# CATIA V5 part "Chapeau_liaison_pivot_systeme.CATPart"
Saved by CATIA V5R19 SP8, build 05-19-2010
Part number: Chapeau_liaison_pivot_systeme
Bounding box of the stored display mesh (mm): x -30 to 30, y -30 to 30, z 1240 to 1260
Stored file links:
  G:\EU_thinkMotion\CFAO_2010\MMS_groupe2\MMS_groupe2\OK\nrosalie\nrosalie_cfao_support_d_arme_legere_final\Chapeau_liaison_pivot_systeme.CATPart
  G:\EU_thinkMotion\CFAO_2010\MMS_groupe2\MMS_groupe2\OK\nrosalie\nrosalie_cfao_support_d_arme_legere_final\nrosalie_Support_d_arme_legere.CATProduct
  G:\EU_thinkMotion\CFAO_2010\MMS_groupe2\MMS_groupe2\OK\nrosalie\nrosalie_cfao_support_d_arme_legere_final\Squelette_Colone.CATPart
  G:\EU_thinkMotion\CFAO_2010\MMS_groupe2\MMS_groupe2\OK\nrosalie\nrosalie_cfao_support_d_arme_legere_final\Axe_liaison_pivot.CATPart
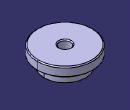
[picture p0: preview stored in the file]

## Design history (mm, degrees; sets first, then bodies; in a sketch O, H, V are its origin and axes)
Set1
  Sketch1 on Plane1, origin (0, 0, 1250), H (1, 0, 0), V (0, 1, 0)
    circle A1 centre (0, 0) radius 30
    reference projected point E1 (0, 0) from Point1
    radius A1 = 30
    concentricity: A1 E1
Set2
  Plane1 "Plan_limite_superieur_colonne": linked copy from another document
  Point1 "Centre_plan_limite_superieur_colonne": linked copy from another document
  DatumCurve1: linked copy from another document
Body1 (main body)
  Pad1: profile Sketch1, direction (0, 0, 1), length 10
  Sketch2 on end face of Pad1, origin (0, 0, 1260), H (1, 0, 0), V (0, 1, 0)
    point P1 (0, 0)
    reference projected circle E1 centre (0, 0) radius 30 from edge [face of Pad1 from Sketch1.A1 | end face of Pad1]
    concentricity: P1 E1
  Hole1: placed by Sketch2, at (0, 0, 1260) direction (0, 0, -1), diameter 12, depth 10
  Chamfer1: length 1, angle 45, on edge [face of Pad1 from Sketch1.A1 | end face of Pad1]; edge [end face of Pad1 | face of Hole1]; edge [start face of Pad1 | face of Pad1 from Sketch1.A1]
  Sketch3 on start face of Pad1, origin (0, 0, 1250), H (1, 0, 0), V (0, -1, 0)
    circle A1 centre (0, 0) radius 20
    reference projected circle E1 centre (0, 0) radius 20 from edge of DatumCurve1
    circle A2 centre (0, 0) radius 22.5
    distance A2 A1 = 2.5
    coincidence: A1 E1
    concentricity: A2 A1
  Pad2: profile Sketch3, direction (0, 0, -1), length 10
  Chamfer2: length 0.5, angle 45, on edge [end face of Pad2 | face of Pad2 from Sketch3.A1]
